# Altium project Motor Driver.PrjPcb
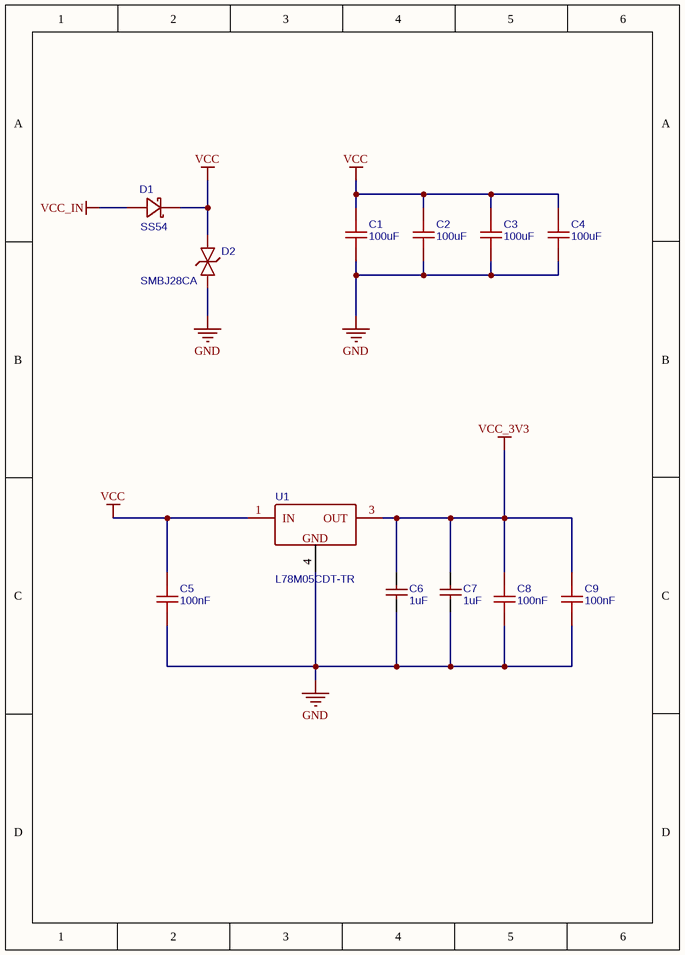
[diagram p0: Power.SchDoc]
5 sheets, 42 parts. Net scope: global (net labels, ports and power ports of the same name join across sheets).
Board file: Motor Driver.PcbDoc
Sheets:
  Power.SchDoc
  Drive.SchDoc
  MCU.SchDoc
  Port.SchDoc
  Interface.SchDoc

## Sheet Power.SchDoc
size 127 x 177 mm; SheetNumber: 1; SheetTotal: 5

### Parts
C1  100uF  [C1206]
C2  100uF  [C1206]
C3  100uF  [C1206]
C4  100uF  [C1206]
C5  100nF  [C0603]
C6  1uF  [C0603]
C7  1uF  [C0603]
C8  100nF  [C0603]
C9  100nF  [C0603]
D1  SS54  [SMA_L4.3-W2.6-LS5.0-RD]
D2  SMBJ28CA  [SMB_L4.6-W3.6-LS5.3-BI]
U1  L78M05CDT-TR  [TO-252-2_L6.5-W6.1-P4.58-LS10.0-TL]

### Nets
GND: C1.2 C2.2 C3.2 C4.2 C5.1 C6.1 C7.1 C8.1 C9.1 D2.1 U1.4(GND)
VCC: C1.1 C2.1 C3.1 C4.1 C5.2 D1.1 D2.2 U1.1(IN)
VCC_3V3: C6.2 C7.2 C8.2 C9.2 U1.3(OUT)
VCC_IN: D1.2

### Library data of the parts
C1-C4 = 100uF: BOM_Manufacturer: Murata Electronics; BOM_Manufacturer Part: GRM31CR61A107ME05L; nameAlias: Capacitance; Contributor: LCSC
C5 C8 C9 = 100nF: BOM_Manufacturer: SAMSUNG; BOM_Manufacturer Part: CL10B104KB8NNNC; nameAlias: Capacitance
C6 C7 = 1uF: BOM_Manufacturer Part: CL10A105KB8NNNC; BOM_Manufacturer: SAMSUNG; nameAlias: Capacitance
D1 = SS54_C727065: BOM_Manufacturer: TWGMC; Contributor: LCSC
D2 = SMBJ28CA_C908204: BOM_Manufacturer: FUXINSEMI; Contributor: LCSC
U1 = L78M05CDT-TR: BOM_Manufacturer: STMicroelectronics

## Sheet Drive.SchDoc
size 203 x 101 mm; SheetNumber: 2; SheetTotal: 5
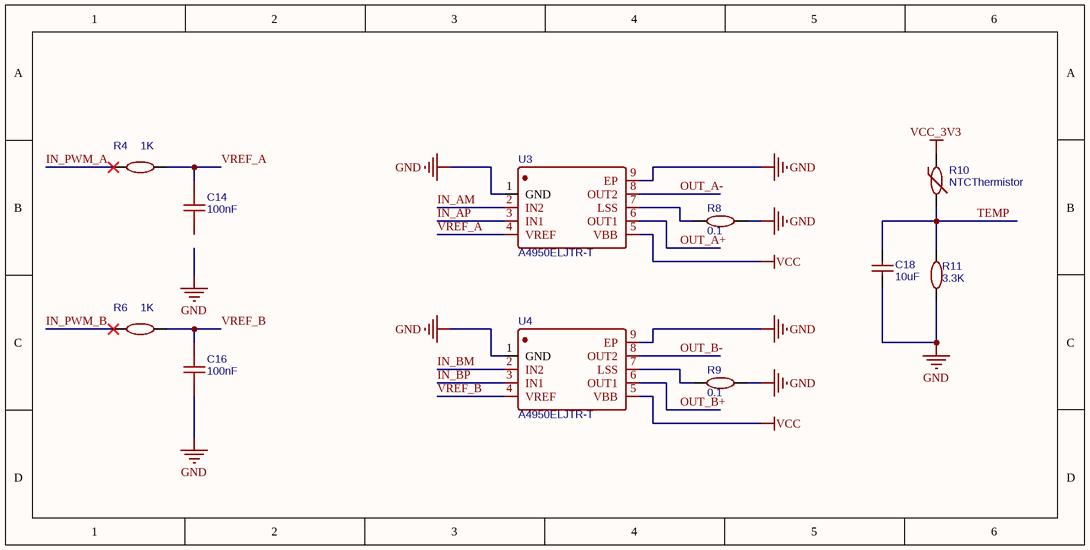
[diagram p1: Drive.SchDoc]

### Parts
C14  100nF  [C0603]
C16  100nF  [C0603]
C18  10uF  [C1206]
R4  1K  [R0603]
R6  1K  [R0603]
R8  0.1  [R1206]
R9  0.1  [R1206]
R10  NTCThermistor  [R0402]
R11  3.3K  [R0603_NEW]
U3  A4950ELJTR-T  [SOIC-8_L4.9-W3.9-P1.27-LS6.0-BL-EP]
U4  A4950ELJTR-T  [SOIC-8_L4.9-W3.9-P1.27-LS6.0-BL-EP]

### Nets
GND: C16.1 C18.1 R8.2 R9.2 R11.1 U3.1(GND) U3.9(EP) U4.1(GND) U4.9(EP)
VCC: U3.5(VBB) U4.5(VBB)
VCC_3V3: R10.1
IN_AM: U3.2(IN2)
IN_AP: U3.3(IN1)
IN_BM: U4.2(IN2)
IN_BP: U4.3(IN1)
IN_PWM_A: R4.1
IN_PWM_B: R6.1
OUT_A+: U3.6(OUT1)
OUT_A-: U3.8(OUT2)
OUT_B+: U4.6(OUT1)
OUT_B-: U4.8(OUT2)
TEMP: C18.2 R10.2 R11.2
VREF_A: C14.2 R4.2 U3.4(VREF)
VREF_B: C16.2 R6.2 U4.4(VREF)
NetR8_1: R8.1 U3.7(LSS)
NetR9_1: R9.1 U4.7(LSS)

Not connected (* = marked no-connect by the designer): C14 1

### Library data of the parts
C14 C16 = 100nF: as C5 on sheet Power
C18 = 10uF: BOM_Manufacturer Part: CL31A106KBHNNNE; BOM_Manufacturer: SAMSUNG; nameAlias: Capacitance
R4 R6 = 1K: BOM_Manufacturer: UniOhm; BOM_Manufacturer Part: 0603WAF1001T5E; nameAlias: Resistance (Ohms)
R8 R9 = 0.1: BOM_Manufacturer: UniOhm; BOM_Manufacturer Part: 1206W4F100LT5E; nameAlias: Resistance (Ohms)
R10 = NTCThermistor: BOM_Manufacturer: MuRata; BOM_Manufacturer Part: NCP15XH103F03RC; nameAlias: Value
R11 = 3.3K: BOM_Manufacturer: UniOhm; BOM_Manufacturer Part: 0603WAF3301T5E; nameAlias: Resistance (Ohms)
U3 U4 = A4950ELJTR-T: BOM_Manufacturer: ALLEGRO

## Sheet MCU.SchDoc
size 228 x 127 mm; SheetNumber: 3; SheetTotal: 5
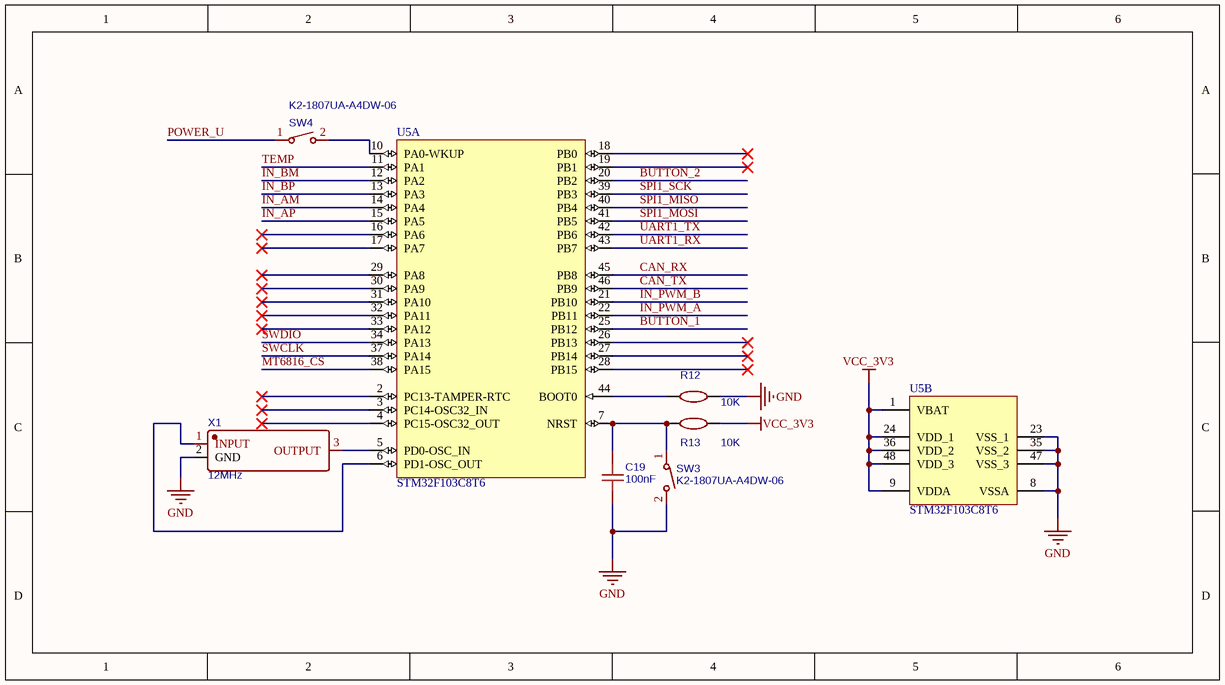
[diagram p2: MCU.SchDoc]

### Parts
C19  100nF  [C0603]
R12  10K  [R0603]
R13  10K  [R0603]
SW3  K2-1807UA-A4DW-06  [KEY-SMD_L4.0-W2.9-L]
SW4  K2-1807UA-A4DW-06  [KEY-SMD_L4.0-W2.9-L]
U5  STM32F103C8T6  [STM-LQFP48_L]  (parts A,B of 2)
X1  12MHz  [CRYSTAL-SMD_3P-L3.2-W1.3-P1.2-BL]

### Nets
GND: C19.1 R12.2 SW3.2 U5.8(VSSA) U5.23(VSS_1) U5.35(VSS_2) U5.47(VSS_3) X1.2(GND)
VCC_3V3: R13.2 U5.1(VBAT) U5.9(VDDA) U5.24(VDD_1) U5.36(VDD_2) U5.48(VDD_3)
BUTTON_1: U5.25(PB12)
BUTTON_2: U5.20(PB2)
CAN_RX: U5.45(PB8)
CAN_TX: U5.46(PB9)
IN_AM: U5.14(PA4)
IN_AP: U5.15(PA5)
IN_BM: U5.12(PA2)
IN_BP: U5.13(PA3)
IN_PWM_A: U5.22(PB11)
IN_PWM_B: U5.21(PB10)
MT6816_CS: U5.38(PA15)
POWER_U: SW4.1
SPI1_MISO: U5.40(PB4)
SPI1_MOSI: U5.41(PB5)
SPI1_SCK: U5.39(PB3)
SWCLK: U5.37(PA14)
SWDIO: U5.34(PA13)
TEMP: U5.11(PA1)
UART1_RX: U5.43(PB7)
UART1_TX: U5.42(PB6)
NetC19_2: C19.2 R13.1 SW3.1 U5.7(NRST)
NetR12_1: R12.1 U5.44(BOOT0)
NetSW4_2: SW4.2 U5.10(PA0-WKUP)
NetU5_5: U5.5(PD0-OSC_IN) X1.3(OUTPUT)
NetU5_6: U5.6(PD1-OSC_OUT) X1.1(INPUT)

Not connected (* = marked no-connect by the designer): U5 2(PC13-TAMPER-RTC)* 3(PC14-OSC32_IN)* 4(PC15-OSC32_OUT)* 16(PA6)* 17(PA7)* 18(PB0)* 19(PB1)* 26(PB13)* 27(PB14)* 28(PB15)* 29(PA8)* 30(PA9)* 31(PA10)* 32(PA11)* 33(PA12)*

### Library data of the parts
C19 = 100nF: as C5 on sheet Power
R12 R13 = 10K: BOM_Manufacturer: UniOhm; BOM_Manufacturer Part: 0603WAF1002T5E; nameAlias: Resistance (Ohms)
SW3 SW4 = K2-1807UA-A4DW-06: BOM_Manufacturer: Korean Hroparts Elec; Contributor: LCSC
U5 = CMP-0237-00215-3: ARM Cortex-M3 32-bit MCU, 64 KB Flash, 20 KB Internal RAM, 37 I/Os, 48-pin LQFP, -40 to 85 degC, Tray; Supply Voltage(Vcc) min (V): 2; Internal RAM Size (kB): 20; FLASH Size (Prog) (kB): 64; A/D Converter: 2x12-bit (10 Channel); I/Os (High Current): 37; Operating Frequency(F) (Processor speed) (MHz): 72
X1 = 12MHz: BOM_Manufacturer: muRata(村田); BOM_Manufacturer Part: CSTNE12M0G52A000R0; nameAlias: Frequency; Contributor: LCSC

## Sheet Port.SchDoc
size 127 x 177 mm; SheetNumber: 4; SheetTotal: 5
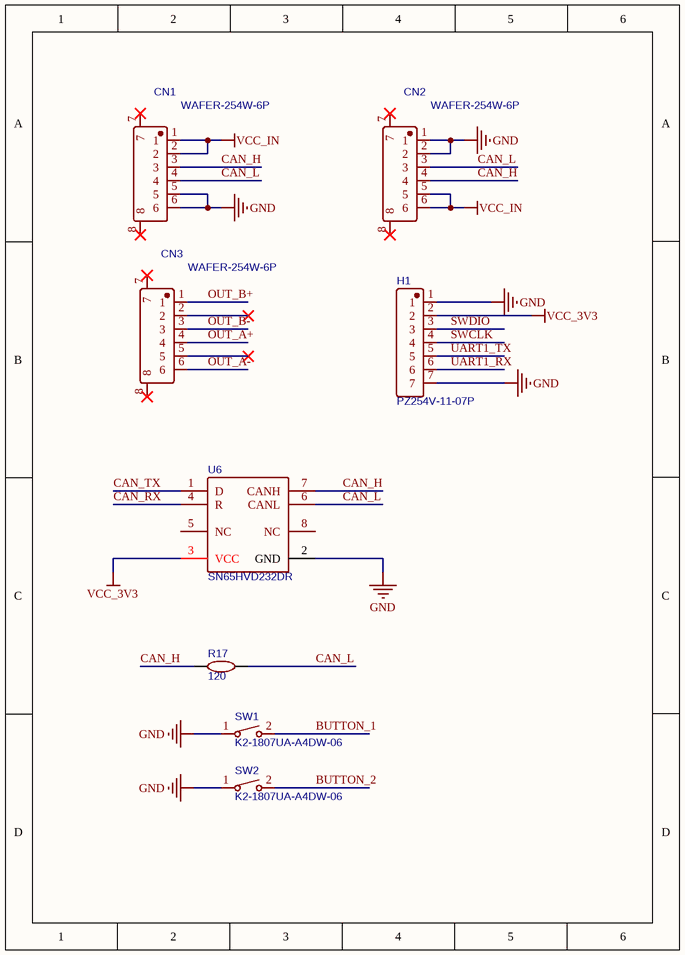
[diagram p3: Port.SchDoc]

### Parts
CN1  WAFER-254W-6P  [CONN-SMD_WAFER-254W-6P]
CN2  WAFER-254W-6P  [CONN-SMD_WAFER-254W-6P]
CN3  WAFER-254W-6P  [CONN-SMD_WAFER-254W-6P]
H1  PZ254V-11-07P  [HDR-TH_7P-P2.54-V-M]
R17  120  [R0603]
SW1  K2-1807UA-A4DW-06  [KEY-SMD_L4.0-W2.9-L]
SW2  K2-1807UA-A4DW-06  [KEY-SMD_L4.0-W2.9-L]
U6  SN65HVD232DR  [SOIC-8_L5.0-W4.0-P1.27-LS6.0-BL]

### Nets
GND: CN1.5 CN1.6 CN2.1 CN2.2 H1.1 H1.7 SW1.1 SW2.1 U6.2(GND)
VCC_3V3: H1.2 U6.3(VCC)
VCC_IN: CN1.1 CN1.2 CN2.5 CN2.6
BUTTON_1: SW1.2
BUTTON_2: SW2.2
CAN_H: CN1.3 CN2.4 R17.1 U6.7(CANH)
CAN_L: CN1.4 CN2.3 R17.2 U6.6(CANL)
CAN_RX: U6.4(R)
CAN_TX: U6.1(D)
OUT_A+: CN3.4
OUT_A-: CN3.6
OUT_B+: CN3.1
OUT_B-: CN3.3
SWCLK: H1.4
SWDIO: H1.3
UART1_RX: H1.6
UART1_TX: H1.5

Not connected (* = marked no-connect by the designer): CN1 7* 8*; CN2 7* 8*; CN3 2* 5* 7* 8*; U6 5(NC) 8(NC)

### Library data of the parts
CN1-CN3 = WAFER-254W-6P: BOM_Manufacturer: XUNPU(讯普); Contributor: LCSC
H1 = PZ254V-11-07P: BOM_Manufacturer: XFCN; Contributor: LCSC
R17 = 120: BOM_Manufacturer: UniOhm; BOM_Manufacturer Part: 0603WAF1200T5E; nameAlias: Resistance (Ohms)
SW1 SW2 = K2-1807UA-A4DW-06: as SW3 on sheet MCU
U6 = SN65HVD232DR: BOM_Manufacturer: TI

## Sheet Interface.SchDoc
size 127 x 127 mm; SheetNumber: 5; SheetTotal: 5
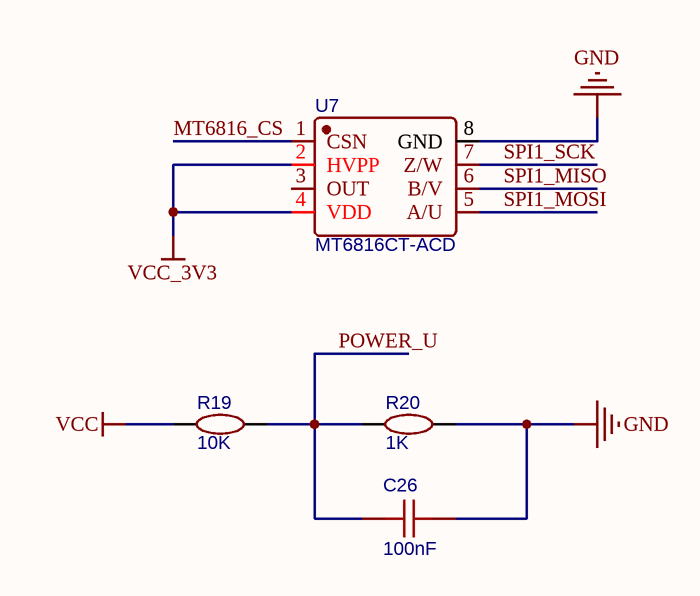
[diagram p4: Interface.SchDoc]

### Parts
C26  100nF  [C0603]
R19  10K  [R0603]
R20  1K  [R0603]
U7  MT6816CT-ACD  [SOP-8_L5.0-W4.0-P1.27-LS6.0-BL]

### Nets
GND: C26.2 R20.2 U7.8(GND)
VCC: R19.1
VCC_3V3: U7.2(HVPP) U7.4(VDD)
MT6816_CS: U7.1(CSN)
POWER_U: C26.1 R19.2 R20.1
SPI1_MISO: U7.6(B/V)
SPI1_MOSI: U7.5(A/U)
SPI1_SCK: U7.7(Z/W)

Not connected (* = marked no-connect by the designer): U7 3(OUT)

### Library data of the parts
C26 = 100nF: as C5 on sheet Power
R19 = 10K: as R12 on sheet MCU
R20 = 1K: as R4 on sheet Drive
U7 = MT6816CT-ACD: BOM_Manufacturer: Magn Tek; Contributor: LCSC

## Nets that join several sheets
GND: Power (11 pins), Drive (9 pins), MCU (8 pins), Port (9 pins), Interface (C26.2 R20.2 U7.8)
VCC: Power (8 pins), Drive (U3.5 U4.5), Interface (R19.1)
VCC_3V3: Power (5 pins), Drive (R10.1), MCU (6 pins), Port (H1.2 U6.3), Interface (U7.2 U7.4)
VCC_IN: Power (D1.2), Port (CN1.1 CN1.2 CN2.5 CN2.6)
BUTTON_1: MCU (U5.25), Port (SW1.2)
BUTTON_2: MCU (U5.20), Port (SW2.2)
CAN_RX: MCU (U5.45), Port (U6.4)
CAN_TX: MCU (U5.46), Port (U6.1)
IN_AM: Drive (U3.2), MCU (U5.14)
IN_AP: Drive (U3.3), MCU (U5.15)
IN_BM: Drive (U4.2), MCU (U5.12)
IN_BP: Drive (U4.3), MCU (U5.13)
IN_PWM_A: Drive (R4.1), MCU (U5.22)
IN_PWM_B: Drive (R6.1), MCU (U5.21)
MT6816_CS: MCU (U5.38), Interface (U7.1)
OUT_A+: Drive (U3.6), Port (CN3.4)
OUT_A-: Drive (U3.8), Port (CN3.6)
OUT_B+: Drive (U4.6), Port (CN3.1)
OUT_B-: Drive (U4.8), Port (CN3.3)
POWER_U: MCU (SW4.1), Interface (C26.1 R19.2 R20.1)
SPI1_MISO: MCU (U5.40), Interface (U7.6)
SPI1_MOSI: MCU (U5.41), Interface (U7.5)
SPI1_SCK: MCU (U5.39), Interface (U7.7)
SWCLK: MCU (U5.37), Port (H1.4)
SWDIO: MCU (U5.34), Port (H1.3)
TEMP: Drive (C18.2 R10.2 R11.2), MCU (U5.11)
UART1_RX: MCU (U5.43), Port (H1.6)
UART1_TX: MCU (U5.42), Port (H1.5)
